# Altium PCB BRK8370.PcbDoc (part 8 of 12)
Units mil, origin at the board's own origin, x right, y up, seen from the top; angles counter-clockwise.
Board outline 8267.72 x 5708.66 mil, 6 copper layers (L1-TOP, L2-GND, L3-PWR, L4-PWR, L5-GND, L6-BOT), stack 68.606 mil thick; 319 components, 516 nets, 2008 pads, 1743 vias.
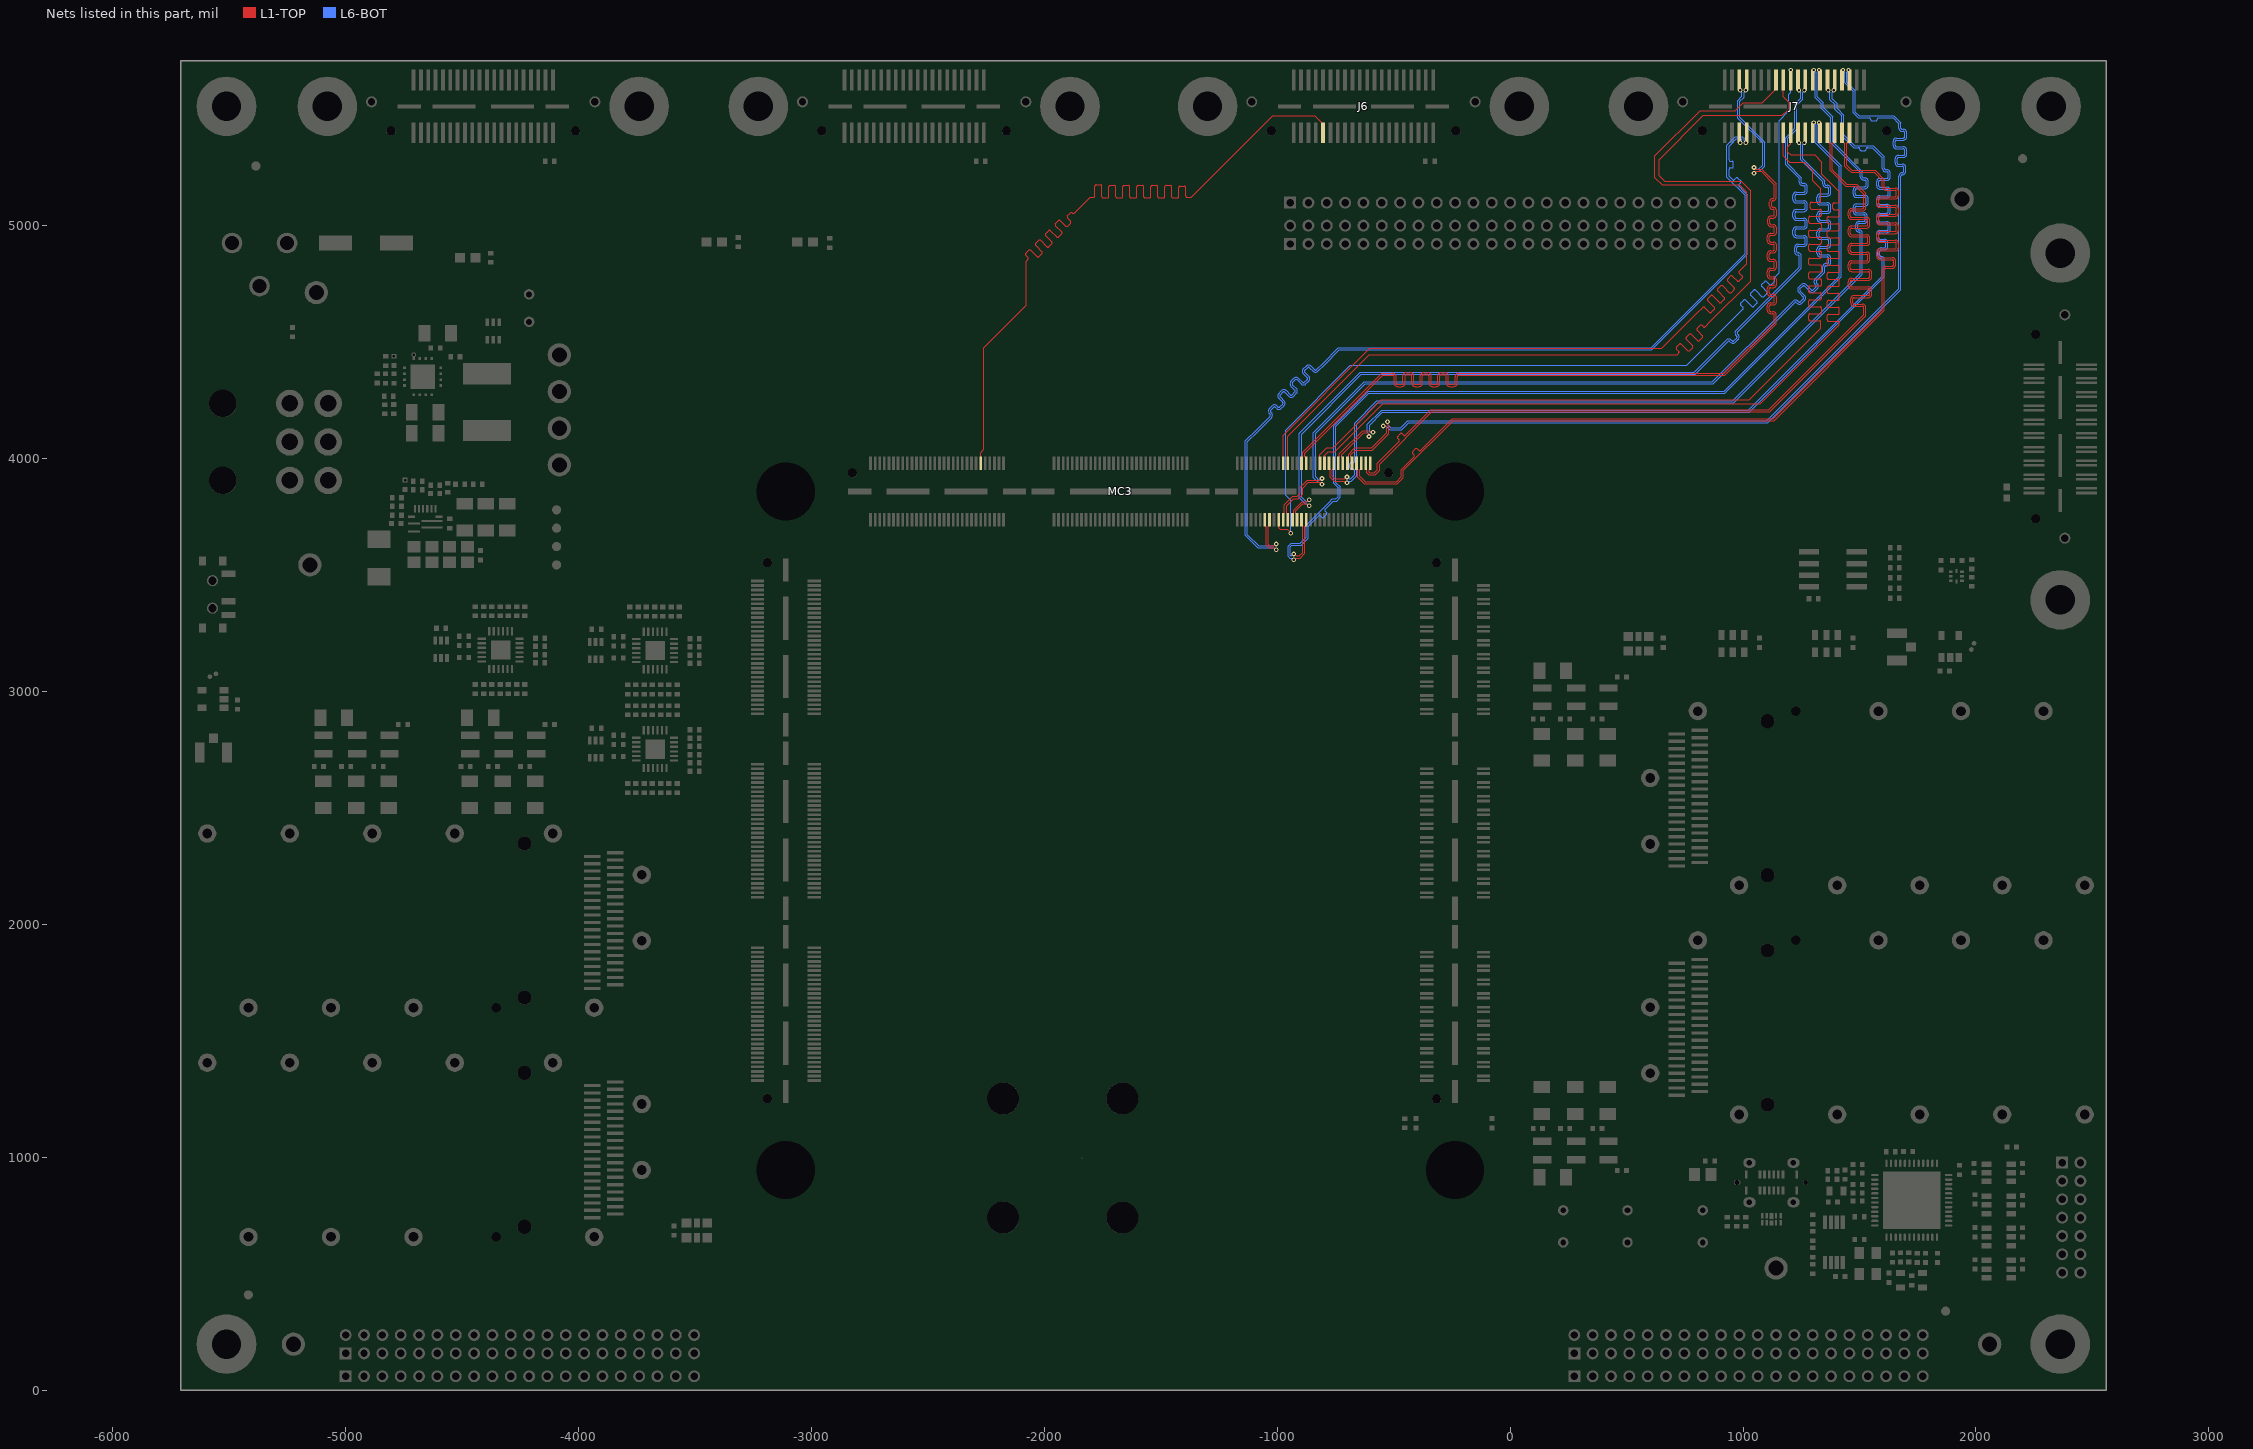
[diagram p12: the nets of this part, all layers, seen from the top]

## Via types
v1: diameter 20, hole 10, L1-TOP to L6-BOT, tented both sides, 957 vias
v2: diameter 18, hole 10, L1-TOP to L6-BOT, tented both sides, 786 vias

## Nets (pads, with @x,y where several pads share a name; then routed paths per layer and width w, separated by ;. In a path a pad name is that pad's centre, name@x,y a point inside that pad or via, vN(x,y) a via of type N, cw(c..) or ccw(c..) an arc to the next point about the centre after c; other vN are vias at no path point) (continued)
PORTC_S27: J6.32 MC3.49 | length 3564.2
  L1-TOP w4.96: MC3.49@-2273.62,3979.92 -2273.62,4025.59 -2259.84,4039.37 -2259.84,4476.38 -2078.74,4657.48 -2078.74,4846.46 -2072.15,4853.04 -2070.4,4854.8 ccw(c-2074.64,4859.03) -2070.4,4863.27 -2079.6,4872.48 cw(c-2075.36,4876.71) -2079.6,4880.95 -2066.89,4893.66 cw(c-2062.65,4889.42) -2058.42,4893.66 -2031.53,4866.78 ccw(c-2027.3,4871.02) -2023.06,4866.78 -2010.35,4879.49 ccw(c-2014.59,4883.73) -2010.35,4887.97 -2037.23,4914.85 cw(c-2032.99,4919.09) -2037.23,4923.32 -2024.52,4936.04 cw(c-2020.28,4931.8) -2016.04,4936.04 -1989.16,4909.16 ccw(c-1984.92,4913.39) -1980.69,4909.16 -1967.97,4921.87 ccw(c-1972.21,4926.1) -1967.97,4930.34 -1994.85,4957.22 cw(c-1990.62,4961.46) -1994.85,4965.7 -1982.14,4978.41 cw(c-1977.9,4974.17) -1973.67,4978.41 -1946.79,4951.53 ccw(c-1942.55,4955.77) -1938.31,4951.53 -1925.6,4964.24 ccw(c-1929.84,4968.48) -1925.6,4972.72 -1952.48,4999.6 cw(c-1948.24,5003.83) -1952.48,5008.07 -1939.77,5020.78 cw(c-1935.53,5016.55) -1931.29,5020.78 -1908.72,4998.21 ccw(c-1904.49,5002.45) -1900.25,4998.21 -1887.54,5010.93 ccw(c-1891.77,5015.16) -1887.54,5019.4 -1900.9,5032.77 cw(c-1896.67,5037.01) -1900.9,5041.24 -1888.19,5053.96 cw(c-1883.95,5049.72) -1879.72,5053.96 ccw(c-1875.48,5058.19) -1871.24,5053.96 -1842.52,5082.68 -1803.15,5122.05 -1791.34,5122.05 -1788.86,5122.05 ccw(c-1788.86,5128.04) -1782.86,5128.04 -1782.86,5169.34 cw(c-1776.87,5169.34) -1776.87,5175.33 -1758.89,5175.33 cw(c-1758.89,5169.34) -1752.9,5169.34 -1752.9,5124.78 ccw(c-1746.91,5124.78) -1746.91,5118.79 -1728.93,5118.79 ccw(c-1728.93,5124.78) -1722.94,5124.78 -1722.94,5166.24 cw(c-1716.95,5166.24) -1716.95,5172.23 -1698.97,5172.23 cw(c-1698.97,5166.24) -1692.98,5166.24 -1692.98,5124.78 ccw(c-1686.98,5124.78) -1686.98,5118.79 -1669,5118.79 ccw(c-1669,5124.78) -1663.01,5124.78 -1663.01,5166.24 cw(c-1657.02,5166.24) -1657.02,5172.23 -1639.04,5172.23 cw(c-1639.04,5166.24) -1633.05,5166.24 -1633.05,5124.78 ccw(c-1627.06,5124.78) -1627.06,5118.79 -1609.08,5118.79 ccw(c-1609.08,5124.78) -1603.09,5124.78 -1603.09,5166.24 cw(c-1597.09,5166.24) -1597.09,5172.23 -1579.12,5172.23 cw(c-1579.12,5166.24) -1573.12,5166.24 -1573.12,5124.78 ccw(c-1567.13,5124.78) -1567.13,5118.79 -1549.15,5118.79 ccw(c-1549.15,5124.78) -1543.16,5124.78 -1543.16,5166.24 cw(c-1537.17,5166.24) -1537.17,5172.23 -1519.19,5172.23 cw(c-1519.19,5166.24) -1513.2,5166.24 -1513.2,5124.78 ccw(c-1507.2,5124.78) -1507.2,5118.79 -1489.23,5118.79 ccw(c-1489.23,5124.78) -1483.23,5124.78 -1483.23,5166.24 cw(c-1477.24,5166.24) -1477.24,5172.23 -1459.26,5172.23 cw(c-1459.26,5166.24) -1453.27,5166.24 -1453.27,5124.78 ccw(c-1447.28,5124.78) -1447.28,5118.79 -1429.3,5118.79 ccw(c-1429.3,5124.78) -1423.31,5124.78 -1423.31,5163.15 cw(c-1417.32,5163.15) -1417.32,5169.14 -1399.34,5169.14 cw(c-1399.34,5163.15) -1393.35,5163.15 -1393.34,5128.04 ccw(c-1387.35,5128.04) -1387.35,5122.05 -1375.98,5122.05 -1369.15,5122.05 -1018.76,5472.44 -839.8,5472.44 -803.12,5435.76 J6.32@-803.12,5399.01
PORTD_C2P_CLK_N: J7.36 MC3.136 | length 4066.2
  L1-TOP w3.3: MC3.136@-1033.46,3736.61 -1033.46,3713.98 -1038.81,3708.63 -1038.81,3631.7 -1031.96,3624.86 -1014.22,3624.86 -1006.22,3632.86 v1(-1003.94,3632.86)
  L6-BOT w3.3: v1(-1003.94,3632.86) -1006.22,3632.86 -1014.22,3624.86 -1079.21,3624.86 -1127.75,3673.4 -1127.75,4072.12 -1080.25,4119.62 -1024.53,4175.34 ccw(c-1034.9,4185.7) -1023.22,4194.56 -1023.22,4194.75 -1024.52,4196.05 -1025.6,4197.13 -1028.03,4199.56 cw(c-1024.03,4203.57) -1028.03,4207.57 -1016.02,4219.57 cw(c-1012.02,4215.57) -1008.02,4219.57 -1003.18,4214.74 ccw(c-992.79,4225.08) -982.42,4214.71 -970.38,4226.75 ccw(c-980.78,4237.08) -969.1,4245.94 -969.1,4246.13 -987.48,4264.52 cw(c-983.48,4268.51) -987.48,4272.52 -975.47,4284.52 cw(c-971.47,4280.52) -967.46,4284.51 ; -967.44,4284.49 -950.43,4267.49 ccw(c-940.04,4277.83) -929.67,4267.46 -917.63,4279.5 ccw(c-928.03,4289.83) -916.35,4298.69 -916.35,4298.88 -934.73,4317.27 cw(c-930.73,4321.26) -934.73,4325.27 -922.72,4337.27 cw(c-918.72,4333.27) -914.71,4337.26 ; -914.69,4337.24 -897.68,4320.24 ccw(c-887.29,4330.58) -876.92,4320.21 -864.88,4332.25 ccw(c-875.28,4342.58) -863.6,4351.44 -863.6,4351.63 -881.98,4370.02 cw(c-877.98,4374.01) -881.98,4378.02 -869.97,4390.02 cw(c-865.97,4386.02) -861.96,4390.01 ; -861.94,4389.99 -846.27,4374.33 ccw(c-835.91,4384.7) -825.54,4374.33 -794.82,4405.05 -733.62,4466.25 608.9,4466.25 1018.66,4876.01 1018.66,5133.29 1004.01,5147.94 982.83,5169.12 cw(c986.84,5173.12) 982.83,5177.12 989.47,5183.76 ccw(c985.47,5187.76) 989.47,5191.76 977.46,5203.77 ccw(c973.46,5199.77) 969.46,5203.77 962.82,5197.13 cw(c958.82,5201.14) 954.82,5197.13 946.45,5205.5 939.82,5212.13 939.82,5242.08 cw(c945.48,5242.08) 945.48,5247.74 953,5247.74 ccw(c953,5253.4) 958.66,5253.4 958.66,5270.38 ccw(c953,5270.38) 953,5276.04 945.48,5276.04 cw(c945.48,5281.7) 939.82,5281.7 939.82,5303.15 939.82,5341.23 971.27,5372.68 993.59,5372.68 995.52,5370.75 995.52,5364.94 988.49,5357.9 v2(988.49,5355.65)
PORTD_C2P_CLK_P: J7.34 MC3.134 | length 4066.2
  L1-TOP w3.3: MC3.134@-1053.15,3736.61 -1053.15,3713.98 -1047.81,3708.63 -1047.81,3627.98 -1035.69,3615.86 -1014.22,3615.86 -1006.22,3607.86 v1(-1003.94,3607.86)
  L6-BOT w3.3: v1(-1003.94,3607.86) -1006.22,3607.86 -1014.22,3615.86 -1082.93,3615.86 -1136.75,3669.68 -1136.75,4075.85 -1086.61,4125.98 -1030.9,4181.7 ccw(c-1034.9,4185.7) -1030.92,4189.72 -1034.39,4193.2 cw(c-1024.03,4203.57) -1034.39,4213.93 -1022.35,4225.98 cw(c-1012.02,4215.57) -1001.66,4225.94 -998.28,4222.56 -996.79,4221.07 ccw(c-992.79,4225.08) -988.79,4221.08 -976.78,4233.08 ccw(c-980.78,4237.08) -976.79,4241.1 ; -976.81,4241.12 -993.81,4258.12 cw(c-983.48,4268.51) -993.84,4278.88 -981.8,4290.92 cw(c-971.47,4280.52) -962.62,4292.21 -962.42,4292.21 -944.04,4273.82 ccw(c-940.04,4277.83) -936.04,4273.83 -924.03,4285.83 ccw(c-928.03,4289.83) -924.04,4293.85 ; -924.06,4293.87 -941.06,4310.87 cw(c-930.73,4321.26) -941.09,4331.63 -929.05,4343.67 cw(c-918.72,4333.27) -909.87,4344.96 -909.67,4344.96 -891.29,4326.57 ccw(c-887.29,4330.58) -883.29,4326.58 -871.28,4338.58 ccw(c-875.28,4342.58) -871.29,4346.6 ; -871.31,4346.62 -888.31,4363.62 cw(c-877.98,4374.01) -888.34,4384.38 -876.3,4396.42 cw(c-865.97,4386.02) -857.12,4397.71 -856.92,4397.71 -839.91,4380.69 ccw(c-835.91,4384.7) -831.91,4380.69 -801.18,4411.42 -737.35,4475.25 605.17,4475.25 1009.66,4879.74 1009.66,5129.56 930.82,5208.4 930.82,5344.96 967.55,5381.68 997.32,5381.68 1004.52,5374.48 1004.52,5364.94 1011.56,5357.9 v2(1011.56,5355.65)
PORTD_P2C_CLK_N: J7.35 MC3.151 | length 4066.2
  L1-TOP w3.3: MC3.151@-875.98,3979.92 -875.98,4002.56 -881.33,4007.9 -881.33,4022.72 -546.81,4357.23 -531.5,4357.23 -503.23,4357.23 cw(c-503.23,4351.57) -497.57,4351.57 -497.57,4323.62 ccw(c-482.91,4323.62) -482.91,4308.96 -465.93,4308.96 ccw(c-465.93,4323.62) -451.27,4323.62 -451.27,4354.28 cw(c-445.61,4354.28) -445.61,4359.94 -428.63,4359.94 cw(c-428.63,4354.28) -422.97,4354.28 -422.97,4323.62 ccw(c-408.31,4323.62) -408.31,4308.96 -391.33,4308.96 ccw(c-391.33,4323.62) -376.67,4323.62 -376.67,4354.28 cw(c-371.01,4354.28) -371.01,4359.94 -354.03,4359.94 cw(c-354.03,4354.28) -348.37,4354.28 -348.37,4323.62 ccw(c-333.71,4323.62) -333.71,4308.96 -316.73,4308.96 ccw(c-316.73,4323.62) -302.07,4323.62 -302.07,4354.28 cw(c-296.41,4354.28) -296.41,4359.94 -279.43,4359.94 cw(c-279.43,4354.28) -273.77,4354.28 -273.77,4323.62 ccw(c-259.11,4323.62) -259.11,4308.96 -242.13,4308.96 ccw(c-242.13,4323.62) -227.47,4323.62 -227.47,4351.57 cw(c-221.81,4351.57) -221.81,4357.23 -215.66,4357.23 921.14,4357.23 1142.86,4578.95 1142.86,4610.24 1142.86,4616.39 ccw(c1128.2,4616.39) 1128.2,4631.05 1118.81,4631.05 cw(c1118.81,4636.71) 1113.15,4636.71 1113.15,4653.69 cw(c1118.81,4653.69) 1118.81,4659.35 1129.4,4659.35 ccw(c1129.4,4674.01) 1144.06,4674.01 1144.06,4690.99 ccw(c1129.4,4690.99) 1129.4,4705.65 1118.81,4705.65 cw(c1118.81,4711.31) 1113.15,4711.31 1113.15,4728.29 cw(c1118.81,4728.29) 1118.81,4733.95 1129.4,4733.95 ccw(c1129.4,4748.61) 1144.06,4748.61 1144.06,4765.59 ccw(c1129.4,4765.59) 1129.4,4780.25 1118.81,4780.25 cw(c1118.81,4785.91) 1113.15,4785.91 1113.15,4802.89 cw(c1118.81,4802.89) 1118.81,4808.55 1129.4,4808.55 ccw(c1129.4,4823.21) 1144.06,4823.21 1144.06,4840.19 ccw(c1129.4,4840.19) 1129.4,4854.85 1118.81,4854.85 cw(c1118.81,4860.51) 1113.15,4860.51 1113.15,4877.49 cw(c1118.81,4877.49) 1118.81,4883.15 1129.4,4883.15 ccw(c1129.4,4897.81) 1144.06,4897.81 1144.06,4914.79 ccw(c1129.4,4914.79) 1129.4,4929.45 1118.81,4929.45 cw(c1118.81,4935.11) 1113.15,4935.11 1113.15,4952.09 cw(c1118.81,4952.09) 1118.81,4957.75 1129.4,4957.75 ccw(c1129.4,4972.41) 1144.06,4972.41 1144.06,4989.39 ccw(c1129.4,4989.39) 1129.4,5004.05 1121.1,5004.05 cw(c1121.1,5009.71) 1115.44,5009.71 1115.44,5026.69 cw(c1121.1,5026.69) 1121.1,5032.35 1129.4,5032.35 ccw(c1129.4,5047.01) 1144.06,5047.01 1144.06,5063.99 ccw(c1129.4,5063.99) 1129.4,5078.65 1128.2,5078.65 cw(c1128.2,5084.31) 1122.54,5084.31 1122.54,5101.29 cw(c1128.2,5101.29) 1128.2,5106.95 ccw(c1128.2,5121.61) 1142.86,5121.61 1142.86,5165.91 1142.86,5179.87 1081.32,5241.41 1057.53,5241.41 1049.53,5249.41 v1(1047.24,5249.41)
  L6-BOT w3.3: v2(988.49,5581.25) 988.49,5579.01 995.52,5571.97 995.52,5554.8 977.5,5536.78 977.5,5461.1 1083.8,5354.8 1083.8,5259.38 1065.84,5241.41 1057.53,5241.41 1049.53,5249.41 v1(1047.24,5249.41)
PORTD_P2C_CLK_P: J7.33 MC3.149 | length 4066.2
  L1-TOP w3.3: MC3.149@-895.67,3979.92 -895.67,4002.56 -890.33,4007.9 -890.33,4026.44 -550.54,4366.23 -531.5,4366.23 -503.23,4366.23 cw(c-503.23,4351.57) -488.57,4351.57 -488.57,4323.62 ccw(c-482.91,4323.62) -482.91,4317.96 -465.93,4317.96 ccw(c-465.93,4323.62) -460.27,4323.62 -460.27,4354.28 cw(c-445.61,4354.28) -445.61,4368.94 -428.63,4368.94 cw(c-428.63,4354.28) -413.97,4354.28 -413.97,4323.62 ccw(c-408.31,4323.62) -408.31,4317.96 -391.33,4317.96 ccw(c-391.33,4323.62) -385.67,4323.62 -385.67,4354.28 cw(c-371.01,4354.28) -371.01,4368.94 -354.03,4368.94 cw(c-354.03,4354.28) -339.37,4354.28 -339.37,4323.62 ccw(c-333.71,4323.62) -333.71,4317.96 -316.73,4317.96 ccw(c-316.73,4323.62) -311.07,4323.62 -311.07,4354.28 cw(c-296.41,4354.28) -296.41,4368.94 -279.43,4368.94 cw(c-279.43,4354.28) -264.77,4354.28 -264.77,4323.62 ccw(c-259.11,4323.62) -259.11,4317.96 -242.13,4317.96 ccw(c-242.13,4323.62) -236.47,4323.62 -236.47,4351.57 cw(c-221.81,4351.57) -221.81,4366.23 -215.66,4366.23 917.41,4366.23 1133.86,4582.68 1133.86,4610.24 1133.86,4616.39 ccw(c1128.2,4616.39) 1128.2,4622.05 1118.81,4622.05 cw(c1118.81,4636.71) 1104.15,4636.71 1104.15,4653.69 cw(c1118.81,4653.69) 1118.81,4668.35 1129.4,4668.35 ccw(c1129.4,4674.01) 1135.06,4674.01 1135.06,4690.99 ccw(c1129.4,4690.99) 1129.4,4696.65 1118.81,4696.65 cw(c1118.81,4711.31) 1104.15,4711.31 1104.15,4728.29 cw(c1118.81,4728.29) 1118.81,4742.95 1129.4,4742.95 ccw(c1129.4,4748.61) 1135.06,4748.61 1135.06,4765.59 ccw(c1129.4,4765.59) 1129.4,4771.25 1118.81,4771.25 cw(c1118.81,4785.91) 1104.15,4785.91 1104.15,4802.89 cw(c1118.81,4802.89) 1118.81,4817.55 1129.4,4817.55 ccw(c1129.4,4823.21) 1135.06,4823.21 1135.06,4840.19 ccw(c1129.4,4840.19) 1129.4,4845.85 1118.81,4845.85 cw(c1118.81,4860.51) 1104.15,4860.51 1104.15,4877.49 cw(c1118.81,4877.49) 1118.81,4892.15 1129.4,4892.15 ccw(c1129.4,4897.81) 1135.06,4897.81 1135.06,4914.79 ccw(c1129.4,4914.79) 1129.4,4920.45 1118.81,4920.45 cw(c1118.81,4935.11) 1104.15,4935.11 1104.15,4952.09 cw(c1118.81,4952.09) 1118.81,4966.75 1129.4,4966.75 ccw(c1129.4,4972.41) 1135.06,4972.41 1135.06,4989.39 ccw(c1129.4,4989.39) 1129.4,4995.05 1121.1,4995.05 cw(c1121.1,5009.71) 1106.44,5009.71 1106.44,5026.69 cw(c1121.1,5026.69) 1121.1,5041.35 1129.4,5041.35 ccw(c1129.4,5047.01) 1135.06,5047.01 1135.06,5063.99 ccw(c1129.4,5063.99) 1129.4,5069.65 1128.2,5069.65 cw(c1128.2,5084.31) 1113.54,5084.31 1113.54,5101.29 cw(c1128.2,5101.29) 1128.2,5115.95 ccw(c1128.2,5121.61) 1133.86,5121.61 1133.86,5165.91 1133.86,5176.14 1077.59,5232.41 1057.53,5232.41 1049.53,5224.41 v1(1047.24,5224.41)
  L6-BOT w3.3: v2(1011.56,5581.25) 1011.56,5579.01 1004.52,5571.97 1004.52,5551.07 986.5,5533.05 986.5,5464.82 1092.8,5358.52 1092.8,5255.65 1069.56,5232.41 1057.53,5232.41 1049.53,5224.41 v1(1047.24,5224.41)
PORTD_S0_D0_P: J7.5 MC3.169 | length 4066
  L1-TOP w3.3: MC3.169@-698.82,3979.92 -698.82,4002.56 -693.48,4007.9 -693.48,4019.26 -667.42,4045.32 -594.82,4045.32 -529.5,4110.64 -529.5,4136.18 -531.52,4138.2 -542.84,4138.2 v1(-544.45,4139.82)
  L6-BOT w3.3: v1(-544.45,4139.82) -542.84,4138.2 -531.52,4138.2 -516.53,4123.21 -465.69,4123.21 -436.2,4152.7 1106.37,4152.7 1678.29,4724.62 1678.29,5161.42 1678.29,5212.23 cw(c1683.95,5212.23) 1683.95,5217.89 ccw(c1683.95,5232.55) 1698.61,5232.55 1698.61,5249.53 ccw(c1683.95,5249.53) 1683.95,5264.19 1667.32,5264.19 cw(c1667.32,5269.85) 1661.66,5269.85 1661.66,5286.83 cw(c1667.32,5286.83) 1667.32,5292.49 1688.63,5292.49 ccw(c1688.63,5307.15) 1703.29,5307.15 1703.29,5324.13 ccw(c1688.63,5324.13) 1688.63,5338.79 1658.95,5338.79 cw(c1658.95,5344.45) 1653.29,5344.45 1653.29,5361.43 cw(c1658.95,5361.43) 1658.95,5367.09 1688.63,5367.09 ccw(c1688.63,5381.75) 1703.29,5381.75 1703.29,5398.73 ccw(c1688.63,5398.73) 1688.63,5413.39 1683.95,5413.39 cw(c1683.95,5419.05) 1678.29,5419.05 1678.29,5425.2 1678.29,5440.74 1647.89,5471.14 1498.28,5471.14 1481.94,5487.48 1481.94,5579.62 1445.52,5616.04 1445.52,5658.69 1452.56,5665.72 v2(1452.56,5667.97)
PORTD_S1_D1_P: J7.6 MC3.173 | length 4247.7
  L1-TOP w3.3: MC3.173@-659.45,3979.92 -659.45,3957.28 -654.11,3951.94 -654.11,3919.32 -626.24,3891.45 -484,3891.45 -458.38,3917.07 -458.38,3948.56 -244.58,4162.36 1134.15,4162.36 1607.43,4635.63 1607.43,4643.06 1607.43,4811.06 cw(c1613.09,4811.06) 1613.09,4816.72 1640.58,4816.72 ccw(c1640.58,4831.38) 1655.24,4831.38 1655.24,4848.36 ccw(c1640.58,4848.36) 1640.58,4863.02 1588.09,4863.02 cw(c1588.09,4868.68) 1582.43,4868.68 1582.43,4885.66 cw(c1588.09,4885.66) 1588.09,4891.32 1652.97,4891.32 ccw(c1652.97,4905.98) 1667.63,4905.98 1667.63,4922.96 ccw(c1652.97,4922.96) 1652.97,4937.62 1588.09,4937.62 cw(c1588.09,4943.28) 1582.43,4943.28 1582.43,4960.26 cw(c1588.09,4960.26) 1588.09,4965.92 1652.97,4965.92 ccw(c1652.97,4980.58) 1667.63,4980.58 1667.63,4997.56 ccw(c1652.97,4997.56) 1652.97,5012.22 1588.09,5012.22 cw(c1588.09,5017.88) 1582.43,5017.88 1582.43,5034.86 cw(c1588.09,5034.86) 1588.09,5040.52 1652.97,5040.52 ccw(c1652.97,5055.18) 1667.63,5055.18 1667.63,5072.16 ccw(c1652.97,5072.16) 1652.97,5086.82 1588.09,5086.82 cw(c1588.09,5092.48) 1582.43,5092.48 1582.43,5109.46 cw(c1588.09,5109.46) 1588.09,5115.12 1652.97,5115.12 ccw(c1652.97,5129.78) 1667.63,5129.78 1667.63,5146.76 ccw(c1652.97,5146.76) 1652.97,5161.42 1613.09,5161.42 cw(c1613.09,5167.08) 1607.43,5167.08 1607.43,5173.23 1607.43,5196.64 1566.72,5237.35 1467.38,5237.35 1445.52,5259.2 1445.52,5353.98 1447.46,5355.91 1450.42,5355.91 1456.77,5362.26 J7.6@1456.77,5399.01
PORTD_S2_D0_N: J7.7 MC3.171 | length 4066
  L1-TOP w3.3: MC3.171@-679.13,3979.92 -679.13,4002.56 -684.48,4007.9 -684.48,4015.53 -663.69,4036.32 -591.09,4036.32 -520.5,4106.91 -520.5,4139.91 -525.16,4144.57 -525.16,4155.88 v1(-526.78,4157.49)
  L6-BOT w3.3: v1(-526.78,4157.49) -525.16,4155.88 -525.16,4144.57 -512.8,4132.21 -469.42,4132.21 -439.93,4161.7 1102.65,4161.7 1669.29,4728.35 1669.29,5161.42 1669.29,5212.23 cw(c1683.95,5212.23) 1683.95,5226.89 ccw(c1683.95,5232.55) 1689.61,5232.55 1689.61,5249.53 ccw(c1683.95,5249.53) 1683.95,5255.19 1667.32,5255.19 cw(c1667.32,5269.85) 1652.66,5269.85 1652.66,5286.83 cw(c1667.32,5286.83) 1667.32,5301.49 1688.63,5301.49 ccw(c1688.63,5307.15) 1694.29,5307.15 1694.29,5324.13 ccw(c1688.63,5324.13) 1688.63,5329.79 1658.95,5329.79 cw(c1658.95,5344.45) 1644.29,5344.45 1644.29,5361.43 cw(c1658.95,5361.43) 1658.95,5376.09 1688.63,5376.09 ccw(c1688.63,5381.75) 1694.29,5381.75 1694.29,5398.73 ccw(c1688.63,5398.73) 1688.63,5404.39 1683.95,5404.39 cw(c1683.95,5419.05) 1669.29,5419.05 1669.29,5425.2 1669.29,5437.01 1665.35,5440.94 1644.16,5462.14 1583.12,5462.14 1581.47,5462.14 ccw(c1581.47,5456.48) 1575.81,5456.48 1575.81,5455.49 cw(c1570.15,5455.49) 1570.15,5449.83 1553.17,5449.83 cw(c1553.17,5455.49) 1547.51,5455.49 1547.51,5456.48 ccw(c1541.85,5456.48) 1541.85,5462.14 1511.57,5462.14 1494.55,5462.14 1488.19,5468.5 1472.94,5483.75 1472.94,5575.89 1436.52,5612.31 1436.52,5658.69 1429.49,5665.72 v2(1429.49,5667.97)
PORTD_S3_D1_N: J7.8 MC3.175 | length 4247.7
  L1-TOP w3.3: MC3.175@-639.76,3979.92 -639.76,3957.28 -645.11,3951.94 -645.11,3923.04 -622.51,3900.45 -487.72,3900.45 -467.38,3920.79 -467.38,3952.29 -424.13,3995.53 -412.57,4007.1 ccw(c-416.57,4011.1) -412.57,4015.1 -418.55,4021.08 cw(c-414.54,4025.08) -418.55,4029.08 -406.54,4041.09 cw(c-402.54,4037.09) -398.54,4041.09 -392.56,4035.11 ccw(c-388.56,4039.12) -384.56,4035.11 -363.38,4056.29 -248.31,4171.36 1130.42,4171.36 1598.43,4639.36 1598.43,4643.06 1598.43,4811.06 cw(c1613.09,4811.06) 1613.09,4825.72 1640.58,4825.72 ccw(c1640.58,4831.38) 1646.24,4831.38 1646.24,4848.36 ccw(c1640.58,4848.36) 1640.58,4854.02 1588.09,4854.02 cw(c1588.09,4868.68) 1573.43,4868.68 1573.43,4885.66 cw(c1588.09,4885.66) 1588.09,4900.32 1652.97,4900.32 ccw(c1652.97,4905.98) 1658.63,4905.98 1658.63,4922.96 ccw(c1652.97,4922.96) 1652.97,4928.62 1588.09,4928.62 cw(c1588.09,4943.28) 1573.43,4943.28 1573.43,4960.26 cw(c1588.09,4960.26) 1588.09,4974.92 1652.97,4974.92 ccw(c1652.97,4980.58) 1658.63,4980.58 1658.63,4997.56 ccw(c1652.97,4997.56) 1652.97,5003.22 1588.09,5003.22 cw(c1588.09,5017.88) 1573.43,5017.88 1573.43,5034.86 cw(c1588.09,5034.86) 1588.09,5049.52 1652.97,5049.52 ccw(c1652.97,5055.18) 1658.63,5055.18 1658.63,5072.16 ccw(c1652.97,5072.16) 1652.97,5077.82 1588.09,5077.82 cw(c1588.09,5092.48) 1573.43,5092.48 1573.43,5109.46 cw(c1588.09,5109.46) 1588.09,5124.12 1652.97,5124.12 ccw(c1652.97,5129.78) 1658.63,5129.78 1658.63,5146.76 ccw(c1652.97,5146.76) 1652.97,5152.42 1613.09,5152.42 cw(c1613.09,5167.08) 1598.43,5167.08 1598.43,5173.23 1598.43,5192.91 1562.99,5228.35 1463.65,5228.35 1454.27,5237.73 1436.52,5255.47 1436.52,5353.98 1434.59,5355.91 1431.62,5355.91 1425.27,5362.26 J7.8@1425.27,5399.01
PORTD_S4_D2_P: J7.9 MC3.165 | length 4066
  L1-TOP w3.3: MC3.165@-738.19,3979.92 -738.19,4002.56 -732.85,4007.9 -732.85,4019.94 -632.83,4119.96 -619.37,4119.96 -619.19,4120.14 -607.91,4120.14 -601.55,4113.78 -590.24,4113.78 v1(-588.62,4112.17)
  L6-BOT w3.3: v1(-588.62,4112.17) -590.24,4113.78 -601.55,4113.78 -603.57,4115.8 -603.57,4142.98 -548.21,4198.33 1026.02,4198.33 1607.43,4779.74 1607.43,4814.96 1607.43,4852.5 ccw(c1592.77,4852.5) 1592.77,4867.16 cw(c1592.76,4872.82) 1587.1,4872.82 1587.1,4889.8 cw(c1592.76,4889.8) 1592.76,4895.46 1606.71,4895.46 ccw(c1606.71,4910.12) 1621.37,4910.12 1621.37,4927.1 ccw(c1606.71,4927.1) 1606.71,4941.76 1588.09,4941.76 cw(c1588.09,4947.42) 1582.43,4947.42 1582.43,4964.4 cw(c1588.09,4964.4) 1588.09,4970.06 1617.77,4970.06 ccw(c1617.77,4984.72) 1632.43,4984.72 1632.43,5001.7 ccw(c1617.77,5001.7) 1617.77,5016.36 1588.09,5016.36 cw(c1588.09,5022.02) 1582.43,5022.02 1582.43,5039 cw(c1588.09,5039) 1588.09,5044.66 1617.77,5044.66 ccw(c1617.77,5059.32) 1632.43,5059.32 1632.43,5076.3 ccw(c1617.77,5076.3) 1617.77,5090.96 1588.09,5090.96 cw(c1588.09,5096.62) 1582.43,5096.62 1582.43,5113.6 cw(c1588.09,5113.6) 1588.09,5119.26 1617.77,5119.26 ccw(c1617.77,5133.92) 1632.43,5133.92 1632.43,5150.9 ccw(c1617.77,5150.9) 1617.77,5165.56 1588.09,5165.56 cw(c1588.09,5171.22) 1582.43,5171.22 1582.43,5188.2 cw(c1588.09,5188.2) 1588.09,5193.86 1617.77,5193.86 ccw(c1617.77,5208.52) 1632.43,5208.52 1632.43,5225.5 ccw(c1617.77,5225.5) 1617.77,5240.16 1613.09,5240.16 cw(c1613.09,5245.82) 1607.43,5245.82 1607.43,5251.97 1607.43,5295.07 1594.42,5308.07 1558.8,5343.69 1480.06,5343.69 1433.4,5390.35 1433.4,5474.62 1403.74,5504.27 1403.74,5523.8 1382.42,5545.12 1382.42,5571.97 1389.46,5579.01 v2(1389.46,5581.25)
PORTD_S5_D3_P: J7.10 MC3.177 | length 4247.7
  L1-TOP w3.3: MC3.177@-620.08,3979.92 -620.08,3957.28 -614.74,3951.94 -614.74,3937.68 -607.53,3930.48 -578.83,3930.48 -560.74,3948.56 -560.74,3976.12 -337.2,4199.66 1113.96,4199.66 1527.56,4613.26 1527.56,4625.98 1527.56,4647.98 ccw(c1512.9,4647.98) 1512.9,4662.64 1477.15,4662.64 cw(c1477.15,4668.3) 1471.49,4668.3 1471.49,4685.28 cw(c1477.15,4685.28) 1477.15,4690.94 1537.9,4690.94 ccw(c1537.9,4705.6) 1552.56,4705.6 1552.56,4722.58 ccw(c1537.9,4722.58) 1537.9,4737.24 1466.37,4737.24 cw(c1466.37,4742.9) 1460.71,4742.9 1460.71,4759.88 cw(c1466.37,4759.88) 1466.37,4765.54 1537.9,4765.54 ccw(c1537.9,4780.2) 1552.56,4780.2 1552.56,4797.18 ccw(c1537.9,4797.18) 1537.9,4811.84 1466.37,4811.84 cw(c1466.37,4817.5) 1460.71,4817.5 1460.71,4834.48 cw(c1466.37,4834.48) 1466.37,4840.14 1530.47,4840.14 ccw(c1530.47,4854.8) 1545.13,4854.8 1545.13,4871.78 ccw(c1530.47,4871.78) 1530.47,4886.44 1466.37,4886.44 cw(c1466.37,4892.1) 1460.71,4892.1 1460.71,4909.08 cw(c1466.37,4909.08) 1466.37,4914.74 1530.47,4914.74 ccw(c1530.47,4929.4) 1545.13,4929.4 1545.13,4946.38 ccw(c1530.47,4946.38) 1530.47,4961.04 1466.37,4961.04 cw(c1466.37,4966.7) 1460.71,4966.7 1460.71,4983.68 cw(c1466.37,4983.68) 1466.37,4989.34 1530.47,4989.34 ccw(c1530.47,5004) 1545.13,5004 1545.13,5020.98 ccw(c1530.47,5020.98) 1530.47,5035.64 1466.37,5035.64 cw(c1466.37,5041.3) 1460.71,5041.3 1460.71,5058.28 cw(c1466.37,5058.28) 1466.37,5063.94 1512.9,5063.94 ccw(c1512.9,5078.6) 1527.56,5078.6 1527.56,5122.05 1527.56,5138.71 1487.98,5178.29 1444.67,5178.29 1443.38,5179.59 1382.52,5240.44 1382.52,5353.98 1384.46,5355.91 1387.42,5355.91 1393.77,5362.26 J7.10@1393.77,5399.01
PORTD_S6_D2_N: J7.11 MC3.167 | length 4066
  L1-TOP w3.3: MC3.167@-718.5,3979.92 -718.5,4002.56 -723.85,4007.9 -723.85,4016.21 -629.1,4110.96 -615.64,4110.96 -615.46,4111.14 -611.64,4111.14 -607.91,4107.42 -607.91,4096.1 v1(-606.3,4094.49)
  L6-BOT w3.3: v1(-606.3,4094.49) -607.91,4096.1 -607.91,4107.42 -612.57,4112.07 -612.57,4146.71 -551.94,4207.33 1022.3,4207.33 1598.43,4783.46 1598.43,4814.96 1598.43,4852.5 ccw(c1592.77,4852.5) 1592.77,4858.16 cw(c1592.76,4872.82) 1578.1,4872.82 1578.1,4889.8 cw(c1592.76,4889.8) 1592.76,4904.46 1606.71,4904.46 ccw(c1606.71,4910.12) 1612.37,4910.12 1612.37,4927.1 ccw(c1606.71,4927.1) 1606.71,4932.76 1588.09,4932.76 cw(c1588.09,4947.42) 1573.43,4947.42 1573.43,4964.4 cw(c1588.09,4964.4) 1588.09,4979.06 1617.77,4979.06 ccw(c1617.77,4984.72) 1623.43,4984.72 1623.43,5001.7 ccw(c1617.77,5001.7) 1617.77,5007.36 1588.09,5007.36 cw(c1588.09,5022.02) 1573.43,5022.02 1573.43,5039 cw(c1588.09,5039) 1588.09,5053.66 1617.77,5053.66 ccw(c1617.77,5059.32) 1623.43,5059.32 1623.43,5076.3 ccw(c1617.77,5076.3) 1617.77,5081.96 1588.09,5081.96 cw(c1588.09,5096.62) 1573.43,5096.62 1573.43,5113.6 cw(c1588.09,5113.6) 1588.09,5128.26 1617.77,5128.26 ccw(c1617.77,5133.92) 1623.43,5133.92 1623.43,5150.9 ccw(c1617.77,5150.9) 1617.77,5156.56 1588.09,5156.56 cw(c1588.09,5171.22) 1573.43,5171.22 1573.43,5188.2 cw(c1588.09,5188.2) 1588.09,5202.86 1617.77,5202.86 ccw(c1617.77,5208.52) 1623.43,5208.52 1623.43,5225.5 ccw(c1617.77,5225.5) 1617.77,5231.16 1613.09,5231.16 cw(c1613.09,5245.82) 1598.43,5245.82 1598.43,5251.97 1598.43,5291.34 1581.69,5308.07 1555.07,5334.69 1536.48,5334.69 1534.83,5334.69 ccw(c1534.83,5329.03) 1529.17,5329.03 1529.17,5328.03 cw(c1523.51,5328.03) 1523.51,5322.37 1506.53,5322.37 cw(c1506.53,5328.03) 1500.87,5328.03 1500.87,5329.03 ccw(c1495.21,5329.03) 1495.21,5334.69 1482.83,5334.69 1476.33,5334.69 1473.7,5337.33 1424.4,5386.63 1424.4,5470.9 1394.74,5500.55 1394.74,5520.07 1373.42,5541.39 1373.42,5571.97 1366.39,5579.01 v2(1366.39,5581.25)
PORTD_S7_D3_N: J7.12 MC3.179 | length 4247.7
  L1-TOP w3.3: MC3.179@-600.39,3979.92 -600.39,3957.28 -605.74,3951.94 -605.74,3941.41 -603.8,3939.48 -582.55,3939.48 -569.74,3952.29 -569.74,3979.85 -501.17,4048.42 -477.53,4072.06 ccw(c-481.53,4076.06) -477.53,4080.06 -483.51,4086.04 cw(c-479.51,4090.04) -483.51,4094.04 -471.5,4106.05 cw(c-467.5,4102.05) -463.5,4106.05 -457.52,4100.07 ccw(c-453.52,4104.08) -449.52,4100.07 -428.34,4121.25 -340.93,4208.66 1110.24,4208.66 1518.56,4616.98 1518.56,4625.98 1518.56,4647.98 ccw(c1512.9,4647.98) 1512.9,4653.64 1477.15,4653.64 cw(c1477.15,4668.3) 1462.49,4668.3 1462.49,4685.28 cw(c1477.15,4685.28) 1477.15,4699.94 1537.9,4699.94 ccw(c1537.9,4705.6) 1543.56,4705.6 1543.56,4722.58 ccw(c1537.9,4722.58) 1537.9,4728.24 1466.37,4728.24 cw(c1466.37,4742.9) 1451.71,4742.9 1451.71,4759.88 cw(c1466.37,4759.88) 1466.37,4774.54 1537.9,4774.54 ccw(c1537.9,4780.2) 1543.56,4780.2 1543.56,4797.18 ccw(c1537.9,4797.18) 1537.9,4802.84 1466.37,4802.84 cw(c1466.37,4817.5) 1451.71,4817.5 1451.71,4834.48 cw(c1466.37,4834.48) 1466.37,4849.14 1530.47,4849.14 ccw(c1530.47,4854.8) 1536.13,4854.8 1536.13,4871.78 ccw(c1530.47,4871.78) 1530.47,4877.44 1466.37,4877.44 cw(c1466.37,4892.1) 1451.71,4892.1 1451.71,4909.08 cw(c1466.37,4909.08) 1466.37,4923.74 1530.47,4923.74 ccw(c1530.47,4929.4) 1536.13,4929.4 1536.13,4946.38 ccw(c1530.47,4946.38) 1530.47,4952.04 1466.37,4952.04 cw(c1466.37,4966.7) 1451.71,4966.7 1451.71,4983.68 cw(c1466.37,4983.68) 1466.37,4998.34 1530.47,4998.34 ccw(c1530.47,5004) 1536.13,5004 1536.13,5020.98 ccw(c1530.47,5020.98) 1530.47,5026.64 1466.37,5026.64 cw(c1466.37,5041.3) 1451.71,5041.3 1451.71,5058.28 cw(c1466.37,5058.28) 1466.37,5072.94 1512.9,5072.94 ccw(c1512.9,5078.6) 1518.56,5078.6 1518.56,5122.05 1518.56,5134.98 1484.25,5169.29 1440.94,5169.29 1373.52,5236.71 1373.52,5353.98 1371.59,5355.91 1368.62,5355.91 1362.27,5362.26 J7.12@1362.27,5399.01
PORTD_S8_D4_P: J7.13 MC3.161 | length 4066.2
  L1-TOP w3.3: MC3.161@-777.56,3979.92 -777.56,3957.28 -772.22,3951.94 -772.22,3919.32 -756.16,3903.26 -711.07,3903.26 -703.07,3895.26 v1(-700.79,3895.26)
  L6-BOT w3.3: v1(-700.79,3895.26) -698.5,3895.26 -690.5,3903.26 -681.51,3903.26 -659.17,3925.61 -659.17,4148.06 -568.24,4238.98 960.37,4238.98 1512.94,4791.55 1512.94,4887.14 1512.94,4966.26 ccw(c1498.28,4966.26) 1498.28,4980.92 cw(c1498.28,4986.58) 1492.62,4986.58 1492.62,5003.56 cw(c1498.28,5003.56) 1498.28,5009.22 1519.08,5009.22 ccw(c1519.08,5023.88) 1533.74,5023.88 1533.74,5040.86 ccw(c1519.08,5040.86) 1519.08,5055.52 1487.1,5055.52 cw(c1487.1,5061.18) 1481.44,5061.18 1481.44,5078.16 cw(c1487.1,5078.16) 1487.1,5083.82 1523.28,5083.82 ccw(c1523.28,5098.48) 1537.94,5098.48 1537.94,5115.46 ccw(c1523.28,5115.46) 1523.28,5130.12 1487.1,5130.12 cw(c1487.1,5135.78) 1481.44,5135.78 1481.44,5152.76 cw(c1487.1,5152.76) 1487.1,5158.42 1523.28,5158.42 ccw(c1523.28,5173.08) 1537.94,5173.08 1537.94,5190.06 ccw(c1523.28,5190.06) 1523.28,5204.72 1518.6,5204.72 cw(c1518.6,5210.38) 1512.94,5210.38 1512.94,5216.54 1512.94,5232.07 1384.7,5360.31 1384.7,5467.48 1344.77,5507.41 1344.77,5527.65 1319.52,5552.9 1319.52,5658.69 1326.56,5665.72 v2(1326.56,5667.97)
PORTD_S9_D5_P: J7.14 MC3.150 | length 4066
  L1-TOP w3.3: v1(-929.13,3589.55) -926.85,3589.55 -918.85,3581.55 -905.05,3581.55 -890.33,3596.27 -890.33,3708.63 -895.67,3713.98 MC3.150@-895.67,3736.61
  L6-BOT w3.3: v1(-929.13,3589.55) -931.42,3589.55 -939.42,3581.55 -942.28,3581.55 -944.21,3583.49 -944.21,3620.37 -936.7,3627.89 -897.16,3627.89 -866.82,3658.23 -866.82,3709.57 -843.66,3732.73 -822.49,3753.91 cw(c-818.48,3749.91) -814.48,3753.91 -808.51,3747.93 ccw(c-804.5,3751.94) -800.5,3747.93 -788.49,3759.94 ccw(c-792.5,3763.94) -788.49,3767.94 -794.47,3773.92 cw(c-790.47,3777.92) -794.47,3781.92 -769.69,3806.7 -759.06,3817.34 -745.43,3817.34 -730.03,3832.73 -730.03,3878.21 -748.16,3896.34 -748.16,4055.12 -748.16,4137.69 -606.22,4279.63 922.28,4279.63 1422.39,4779.74 1422.39,5256.51 1370.82,5308.07 1319.52,5359.37 1319.52,5433.09 1326.56,5440.12 v2(1326.56,5442.37)
PORTD_S10_D4_N: J7.15 MC3.163 | length 4066.2
  L1-TOP w3.3: MC3.163@-757.87,3979.92 -757.87,3957.28 -763.22,3951.94 -763.22,3923.04 -752.43,3912.26 -711.07,3912.26 -703.07,3920.26 v1(-700.79,3920.26)
  L6-BOT w3.3: v1(-700.79,3920.26) -698.5,3920.26 -690.5,3912.26 -685.24,3912.26 -668.17,3929.33 -668.17,3946.69 -668.17,3948.34 ccw(c-673.83,3948.34) -673.83,3954 -682.28,3954 cw(c-682.28,3959.66) -687.94,3959.66 -687.94,3976.64 cw(c-682.28,3976.64) -682.28,3982.3 -673.83,3982.3 ccw(c-673.83,3987.96) -668.17,3987.96 -668.17,4015.75 -668.17,4151.79 -571.97,4247.98 956.65,4247.98 1503.94,4795.28 1503.94,4887.14 1503.94,4966.26 ccw(c1498.28,4966.26) 1498.28,4971.92 cw(c1498.28,4986.58) 1483.62,4986.58 1483.62,5003.56 cw(c1498.28,5003.56) 1498.28,5018.22 1519.08,5018.22 ccw(c1519.08,5023.88) 1524.74,5023.88 1524.74,5040.86 ccw(c1519.08,5040.86) 1519.08,5046.52 1487.1,5046.52 cw(c1487.1,5061.18) 1472.44,5061.18 1472.44,5078.16 cw(c1487.1,5078.16) 1487.1,5092.82 1523.28,5092.82 ccw(c1523.28,5098.48) 1528.94,5098.48 1528.94,5115.46 ccw(c1523.28,5115.46) 1523.28,5121.12 1487.1,5121.12 cw(c1487.1,5135.78) 1472.44,5135.78 1472.44,5152.76 cw(c1487.1,5152.76) 1487.1,5167.42 1523.28,5167.42 ccw(c1523.28,5173.08) 1528.94,5173.08 1528.94,5190.06 ccw(c1523.28,5190.06) 1523.28,5195.72 1518.6,5195.72 cw(c1518.6,5210.38) 1503.94,5210.38 1503.94,5216.54 1503.94,5228.35 1375.7,5356.58 1375.7,5463.75 1335.77,5503.68 1335.77,5523.93 1310.52,5549.17 1310.52,5658.69 1303.49,5665.72 v2(1303.49,5667.97)
PORTD_S11_D5_N: J7.16 MC3.152 | length 4066
  L1-TOP w3.3: v1(-929.13,3564.55) -926.85,3564.55 -918.85,3572.55 -901.32,3572.55 -881.33,3592.54 -881.33,3708.63 -875.98,3713.98 MC3.152@-875.98,3736.61
  L6-BOT w3.3: v1(-929.13,3564.55) -931.42,3564.55 -939.42,3572.55 -946,3572.55 -953.21,3579.76 -953.21,3624.1 -940.42,3636.89 -900.89,3636.89 -875.82,3661.96 -875.82,3713.3 -776.05,3813.07 -762.78,3826.34 -749.15,3826.34 -739.03,3836.46 -739.03,3874.48 -757.16,3892.61 -757.16,4055.12 -757.16,4141.42 -609.94,4288.63 918.56,4288.63 1413.39,4783.46 1413.39,5252.78 1358.1,5308.07 1310.52,5355.65 1310.52,5433.09 1303.49,5440.12 v2(1303.49,5442.37)
PORTD_S12_D6_P: J7.17 MC3.146 | length 4066.1
  L1-TOP w3.3: MC3.146@-935.04,3736.61 -935.04,3759.25 -929.7,3764.59 -929.7,3778.51 -893.68,3814.53 -872.49,3814.53 -864.49,3822.53 v1(-862.2,3822.53)
  L6-BOT w3.3: v1(-862.2,3822.53) -864.49,3822.53 -872.49,3814.53 -876.09,3814.53 -895.72,3834.15 -895.72,4105.11 -639.89,4360.93 794.01,4360.93 872.84,4439.77 935.28,4502.21 cw(c939.28,4498.2) 943.3,4502.19 ; 943.31,4502.18 946.61,4498.88 ccw(c956.97,4509.24) 967.34,4498.88 979.38,4510.92 ccw(c968.98,4521.25) 979.35,4531.62 978.05,4532.91 976.01,4534.95 cw(c980.02,4538.95) 976.02,4542.95 980.37,4547.3 1250.85,4817.78 1250.85,4826.77 1250.85,4868.04 ccw(c1236.19,4868.04) 1236.19,4882.7 1236.06,4882.7 cw(c1236.06,4888.36) 1230.4,4888.36 1230.4,4905.34 cw(c1236.06,4905.34) 1236.06,4911 1261.19,4911 ccw(c1261.19,4925.66) 1275.85,4925.66 1275.85,4942.64 ccw(c1261.19,4942.64) 1261.19,4957.3 1228.84,4957.3 cw(c1228.84,4962.96) 1223.18,4962.96 1223.18,4979.94 cw(c1228.84,4979.94) 1228.84,4985.6 1261.19,4985.6 ccw(c1261.19,5000.26) 1275.85,5000.26 1275.85,5017.24 ccw(c1261.19,5017.24) 1261.19,5031.9 1228.84,5031.9 cw(c1228.84,5037.56) 1223.18,5037.56 1223.18,5054.54 cw(c1228.84,5054.54) 1228.84,5060.2 1261.19,5060.2 ccw(c1261.19,5074.86) 1275.85,5074.86 1275.85,5091.84 ccw(c1261.19,5091.84) 1261.19,5106.5 1228.84,5106.5 cw(c1228.84,5112.16) 1223.18,5112.16 1223.18,5129.14 cw(c1228.84,5129.14) 1228.84,5134.8 1261.19,5134.8 ccw(c1261.19,5149.46) 1275.85,5149.46 1275.85,5166.44 ccw(c1261.19,5166.44) 1261.19,5181.1 1256.51,5181.1 cw(c1256.51,5186.76) 1250.85,5186.76 1250.85,5192.91 1250.85,5206.23 1191.79,5265.29 1191.79,5374.32 1231.16,5413.69 1231.16,5516.77 1256.42,5542.04 1256.42,5571.97 1263.46,5579.01 v2(1263.46,5581.25)
PORTD_S13_D7_P: J7.18 MC3.142 | length 4066.2
  L1-TOP w3.3: MC3.142@-974.41,3736.61 -974.41,3759.25 -969.07,3764.59 -969.07,3801.33 -933.5,3836.9 -913.6,3836.9 -900.45,3850.05 -900.45,3876.68 -870.88,3906.24 -818.35,3906.24 -810.35,3914.24 v1(-808.07,3914.24)
  L6-BOT w3.3: v1(-808.07,3914.24) -810.35,3914.24 -818.35,3906.24 -821.21,3906.24 -835.73,3920.76 -835.73,4107.61 -623.05,4320.28 872.38,4320.28 1182.61,4630.52 1221.51,4669.42 cw(c1225.52,4665.41) 1229.54,4669.4 ; 1229.54,4669.39 1232.25,4666.69 ccw(c1242.61,4677.05) 1252.98,4666.69 1265.02,4678.73 ccw(c1254.62,4689.06) 1264.98,4699.43 1250.81,4713.61 1244.57,4719.84 cw(c1248.58,4723.83) 1244.58,4727.84 1256.59,4739.84 cw(c1260.59,4735.84) 1264.6,4739.83 1286.77,4717.66 ccw(c1297.17,4728) 1307.53,4717.63 1319.58,4729.68 ccw(c1309.17,4740.01) 1320.86,4748.86 1320.86,4749.05 1315.01,4754.9 cw(c1319.01,4758.91) 1315.01,4762.91 1319.36,4767.26 1351.52,4799.42 1351.52,4822.87 cw(c1357.18,4822.87) 1357.18,4828.53 1361.86,4828.53 ccw(c1361.86,4843.19) 1376.52,4843.19 1376.52,4860.17 ccw(c1361.86,4860.17) 1361.86,4874.83 1332.18,4874.83 cw(c1332.18,4880.49) 1326.52,4880.49 1326.52,4897.47 cw(c1332.18,4897.47) 1332.18,4903.13 1361.86,4903.13 ccw(c1361.86,4917.79) 1376.52,4917.79 1376.52,4934.77 ccw(c1361.86,4934.77) 1361.86,4949.43 1332.18,4949.43 cw(c1332.18,4955.09) 1326.52,4955.09 1326.52,4972.07 cw(c1332.18,4972.07) 1332.18,4977.73 1361.86,4977.73 ccw(c1361.86,4992.39) 1376.52,4992.39 1376.52,5009.37 ccw(c1361.86,5009.37) 1361.86,5024.03 1332.18,5024.03 cw(c1332.18,5029.69) 1326.52,5029.69 1326.52,5046.67 cw(c1332.18,5046.67) 1332.18,5052.33 1361.86,5052.33 ccw(c1361.86,5066.99) 1376.52,5066.99 1376.52,5083.97 ccw(c1361.86,5083.97) 1361.86,5098.63 1332.18,5098.63 cw(c1332.18,5104.29) 1326.52,5104.29 1326.52,5121.27 cw(c1332.18,5121.27) 1332.18,5126.93 1361.86,5126.93 ccw(c1361.86,5141.59) 1376.52,5141.59 1376.52,5158.57 ccw(c1361.86,5158.57) 1361.86,5173.23 1357.18,5173.23 cw(c1357.18,5178.89) 1351.52,5178.89 1351.52,5185.04 1351.52,5191.79 1313.45,5229.86 1256.52,5286.78 1256.52,5346.37 1263.56,5353.41 v2(1263.56,5355.65)
PORTD_S14_D6_N: J7.19 MC3.148 | length 4066.2
  L1-TOP w3.3: MC3.148@-915.35,3736.61 -915.35,3759.25 -920.7,3764.59 -920.7,3774.78 -889.95,3805.53 -872.49,3805.53 -864.49,3797.53 v1(-862.2,3797.53)
  L6-BOT w3.3: v1(-862.2,3797.53) -864.49,3797.53 -872.49,3805.53 -879.82,3805.53 -904.72,3830.42 -904.72,4108.84 -643.62,4369.93 790.28,4369.93 866.48,4446.13 928.91,4508.57 cw(c939.28,4498.2) 948.13,4509.89 948.33,4509.89 949.63,4508.59 950.66,4507.55 952.97,4505.24 ccw(c956.97,4509.24) 960.98,4505.24 972.98,4517.25 ccw(c968.98,4521.25) 972.98,4525.25 969.68,4528.56 cw(c980.02,4538.95) 969.66,4549.31 974,4553.66 1241.85,4821.51 1241.85,4826.77 1241.85,4868.04 ccw(c1236.19,4868.04) 1236.19,4873.7 1236.06,4873.7 cw(c1236.06,4888.36) 1221.4,4888.36 1221.4,4905.34 cw(c1236.06,4905.34) 1236.06,4920 1261.19,4920 ccw(c1261.19,4925.66) 1266.85,4925.66 1266.85,4942.64 ccw(c1261.19,4942.64) 1261.19,4948.3 1228.84,4948.3 cw(c1228.84,4962.96) 1214.18,4962.96 1214.18,4979.94 cw(c1228.84,4979.94) 1228.84,4994.6 1261.19,4994.6 ccw(c1261.19,5000.26) 1266.85,5000.26 1266.85,5017.24 ccw(c1261.19,5017.24) 1261.19,5022.9 1228.84,5022.9 cw(c1228.84,5037.56) 1214.18,5037.56 1214.18,5054.54 cw(c1228.84,5054.54) 1228.84,5069.2 1261.19,5069.2 ccw(c1261.19,5074.86) 1266.85,5074.86 1266.85,5091.84 ccw(c1261.19,5091.84) 1261.19,5097.5 1228.84,5097.5 cw(c1228.84,5112.16) 1214.18,5112.16 1214.18,5129.14 cw(c1228.84,5129.14) 1228.84,5143.8 1261.19,5143.8 ccw(c1261.19,5149.46) 1266.85,5149.46 1266.85,5166.44 ccw(c1261.19,5166.44) 1261.19,5172.1 1256.51,5172.1 cw(c1256.51,5186.76) 1241.85,5186.76 1241.85,5192.91 1241.85,5202.5 1182.79,5261.56 1182.79,5378.05 1222.16,5417.42 1222.16,5520.5 1247.42,5545.77 1247.42,5571.97 1240.39,5579.01 v2(1240.39,5581.25)
PORTD_S15_D7_N: J7.20 MC3.144 | length 4066.3
  L1-TOP w3.3: MC3.144@-954.72,3736.61 -954.72,3759.25 -960.07,3764.59 -960.07,3797.61 -929.78,3827.9 -909.87,3827.9 -891.45,3846.32 -891.45,3872.95 -867.16,3897.24 -818.35,3897.24 -810.35,3889.24 v1(-808.07,3889.24)
  L6-BOT w3.3: v1(-808.07,3889.24) -810.35,3889.24 -818.35,3897.24 -824.94,3897.24 -844.73,3917.03 -844.73,4111.34 -626.78,4329.28 868.65,4329.28 1176.25,4636.88 1215.15,4675.78 cw(c1225.52,4665.41) 1234.37,4677.1 1234.56,4677.1 1235.86,4675.8 ; 1235.88,4675.78 1236.71,4674.95 1238.61,4673.05 ccw(c1242.61,4677.05) 1246.61,4673.05 1258.62,4685.06 ccw(c1254.62,4689.06) 1258.62,4693.06 1238.24,4713.44 ; 1238.24,4713.44 cw(c1248.58,4723.83) 1238.22,4734.2 1250.26,4746.24 cw(c1260.59,4735.84) 1269.44,4747.53 1269.64,4747.53 1293.17,4723.99 ccw(c1297.17,4728) 1301.17,4724 1313.18,4736 ccw(c1309.17,4740.01) 1313.16,4744.02 ; v2(1240.49,5355.65) 1240.49,5353.41 1247.52,5346.37 1247.52,5283.06 1300.72,5229.86 1342.52,5188.06 1342.52,5185.04 1342.52,5178.89 ccw(c1357.18,5178.89) 1357.18,5164.23 1361.86,5164.23 cw(c1361.86,5158.57) 1367.52,5158.57 1367.52,5141.59 cw(c1361.86,5141.59) 1361.86,5135.93 1332.18,5135.93 ccw(c1332.18,5121.27) 1317.52,5121.27 1317.52,5104.29 ccw(c1332.18,5104.29) 1332.18,5089.63 1361.86,5089.63 cw(c1361.86,5083.97) 1367.52,5083.97 1367.52,5066.99 cw(c1361.86,5066.99) 1361.86,5061.33 1332.18,5061.33 ccw(c1332.18,5046.67) 1317.52,5046.67 1317.52,5029.69 ccw(c1332.18,5029.69) 1332.18,5015.03 1361.86,5015.03 cw(c1361.86,5009.37) 1367.52,5009.37 1367.52,4992.39 cw(c1361.86,4992.39) 1361.86,4986.73 1332.18,4986.73 ccw(c1332.18,4972.07) 1317.52,4972.07 1317.52,4955.09 ccw(c1332.18,4955.09) 1332.18,4940.43 1361.86,4940.43 cw(c1361.86,4934.77) 1367.52,4934.77 1367.52,4917.79 cw(c1361.86,4917.79) 1361.86,4912.13 1332.18,4912.13 ccw(c1332.18,4897.47) 1317.52,4897.47 1317.52,4880.49 ccw(c1332.18,4880.49) 1332.18,4865.83 1361.86,4865.83 cw(c1361.86,4860.17) 1367.52,4860.17 1367.52,4843.19 cw(c1361.86,4843.19) 1361.86,4837.53 1357.18,4837.53 ccw(c1357.18,4822.87) 1342.52,4822.87 1342.52,4803.15 1338.79,4799.42 1312.99,4773.62 1308.64,4769.27 ccw(c1319.01,4758.91) 1308.64,4748.54 1313.15,4744.04
PORTD_S16: J7.21 MC3.140 | length 4064.5
  L1-TOP w4.96: MC3.140@-994.09,3736.61 -994.09,3702.76 -987.41,3696.07 -956.03,3696.07 -942.28,3682.32 v1(-942.28,3678.96)
  L6-BOT w4.96: v1(-942.28,3678.96) -942.28,3819.66 -964.57,3841.94 -964.57,4121.13 -686.24,4399.46 757.72,4399.46 997.61,4639.35 999.37,4641.1 ccw(c995.13,4645.34) 999.37,4649.58 990.17,4658.78 cw(c994.4,4663.02) 990.17,4667.25 1002.88,4679.97 cw(c1007.12,4675.73) 1011.35,4679.97 1038.23,4653.09 ccw(c1042.47,4657.32) 1046.71,4653.09 1059.42,4665.8 ccw(c1055.18,4670.03) 1059.42,4674.27 1032.54,4701.15 cw(c1036.78,4705.39) 1032.54,4709.63 1045.25,4722.34 cw(c1049.49,4718.1) 1053.73,4722.34 1080.61,4695.46 ccw(c1084.85,4699.7) 1089.08,4695.46 1101.79,4708.17 ccw(c1097.56,4712.41) 1101.79,4716.65 1079.72,4738.72 cw(c1083.96,4742.96) 1079.72,4747.2 1092.43,4759.91 cw(c1096.67,4755.67) 1100.9,4759.91 1113.78,4747.04 ccw(c1118.02,4751.27) 1122.25,4747.04 1134.97,4759.75 ccw(c1130.73,4763.99) 1134.97,4768.22 cw(c1139.2,4772.46) 1134.97,4776.7 1145.67,4787.4 1155.61,4797.34 1155.61,5450.89 1196.85,5492.13 1196.85,5564.04 1204.67,5571.86 v2(1204.67,5667.97)
PORTD_S17: J7.22 MC3.159 | length 4242.4
  L1-TOP w4.96: MC3.159@-797.24,3979.92 -797.24,4012.26 -781.12,4028.38 -753.98,4028.38 -547.36,4235.01 1073.59,4235.01 1413.39,4574.8 1413.39,4580.71 1413.39,4583.19 ccw(c1407.39,4583.19) 1407.39,4589.18 1367.91,4589.18 cw(c1367.91,4595.18) 1361.92,4595.18 1361.92,4613.15 cw(c1367.91,4613.15) 1367.91,4619.15 1407.44,4619.15 ccw(c1407.44,4625.14) 1413.43,4625.14 1413.43,4643.12 ccw(c1407.44,4643.12) 1407.44,4649.11 1367.91,4649.11 cw(c1367.91,4655.1) 1361.92,4655.1 1361.92,4673.08 cw(c1367.91,4673.08) 1367.91,4679.07 1407.44,4679.07 ccw(c1407.44,4685.06) 1413.43,4685.06 1413.43,4703.04 ccw(c1407.44,4703.04) 1407.44,4709.04 1367.91,4709.04 cw(c1367.91,4715.03) 1361.92,4715.03 1361.92,4733.01 cw(c1367.91,4733.01) 1367.91,4739 1407.44,4739 ccw(c1407.44,4744.99) 1413.43,4744.99 1413.43,4762.97 ccw(c1407.44,4762.97) 1407.44,4768.96 1367.91,4768.96 cw(c1367.91,4774.95) 1361.92,4774.95 1361.92,4792.93 cw(c1367.91,4792.93) 1367.91,4798.92 1407.44,4798.92 ccw(c1407.44,4804.92) 1413.43,4804.92 1413.43,4822.89 ccw(c1407.44,4822.89) 1407.44,4828.89 1367.91,4828.89 cw(c1367.91,4834.88) 1361.92,4834.88 1361.92,4852.86 cw(c1367.91,4852.86) 1367.91,4858.85 1407.44,4858.85 ccw(c1407.44,4864.84) 1413.43,4864.84 1413.43,4882.82 ccw(c1407.44,4882.82) 1407.44,4888.81 1367.91,4888.81 cw(c1367.91,4894.81) 1361.92,4894.81 1361.92,4912.78 cw(c1367.91,4912.78) 1367.91,4918.78 1407.44,4918.78 ccw(c1407.44,4924.77) 1413.43,4924.77 1413.43,4942.75 ccw(c1407.44,4942.75) 1407.44,4948.74 1367.91,4948.74 cw(c1367.91,4954.73) 1361.92,4954.73 1361.92,4972.71 cw(c1367.91,4972.71) 1367.91,4978.7 1407.44,4978.7 ccw(c1407.44,4984.69) 1413.43,4984.69 1413.43,5002.67 ccw(c1407.44,5002.67) 1407.44,5008.67 1367.91,5008.67 cw(c1367.91,5014.66) 1361.92,5014.66 1361.92,5032.64 cw(c1367.91,5032.64) 1367.91,5038.63 1407.44,5038.63 ccw(c1407.44,5044.62) 1413.43,5044.62 1413.43,5062.6 ccw(c1407.44,5062.6) 1407.44,5068.59 1392.22,5068.59 cw(c1392.22,5074.58) 1386.23,5074.58 1386.23,5092.56 cw(c1392.22,5092.56) 1392.22,5098.55 1407.39,5098.55 ccw(c1407.39,5104.55) 1413.39,5104.55 1413.39,5137.8 1413.39,5145.67 1338.58,5220.47 1338.58,5271.65 1307.09,5303.15 1204.72,5303.15 1192.91,5314.96 1192.91,5338.58 1204.77,5350.44 J7.22@1204.77,5399.01
PORTD_S18: J7.23 MC3.143 | length 4242.4
  L1-TOP w4.96: MC3.143@-954.72,3979.92 -954.72,4095.72 -605.56,4444.88 716.54,4444.88 721.58,4449.93 723.34,4451.68 ccw(c719.1,4455.92) 723.34,4460.16 714.13,4469.36 cw(c718.37,4473.6) 714.13,4477.83 726.85,4490.55 cw(c731.08,4486.31) 735.32,4490.55 762.2,4463.67 ccw(c766.44,4467.9) 770.68,4463.67 783.39,4476.38 ccw(c779.15,4480.62) 783.39,4484.85 756.51,4511.73 cw(c760.74,4515.97) 756.51,4520.21 769.22,4532.92 cw(c773.46,4528.68) 777.69,4532.92 804.57,4506.04 ccw(c808.81,4510.28) 813.05,4506.04 825.76,4518.75 ccw(c821.52,4522.99) 825.76,4527.23 803.02,4549.97 cw(c807.26,4554.21) 803.02,4558.44 815.73,4571.16 cw(c819.97,4566.92) 824.21,4571.16 829.27,4566.09 ccw(c833.51,4570.33) 837.75,4566.09 862.2,4590.55 1032.48,4760.83 1032.48,5150.68 991.76,5191.41 662.92,5191.41 640.09,5214.24 640.09,5283.36 829.76,5473.04 1168.28,5473.04 1195.45,5500.21 1195.45,5530.19 1173.27,5552.37 J7.23@1173.27,5624.61
PORTD_S19: J7.24 MC3.157 | length 4242.4
  L1-TOP w4.96: MC3.157@-816.93,3979.92 -816.93,4016.56 -788.15,4045.35 -761.01,4045.35 -751.23,4055.12 -554.38,4251.97 1027.56,4251.97 1334.65,4559.06 1334.65,4582.68 1334.65,4585.16 ccw(c1328.65,4585.16) 1328.65,4591.15 1287.58,4591.15 cw(c1287.58,4597.14) 1281.58,4597.14 1281.58,4615.12 cw(c1287.58,4615.12) 1287.58,4621.11 1331.02,4621.11 ccw(c1331.02,4627.11) 1337.01,4627.11 1337.01,4645.09 ccw(c1331.02,4645.09) 1331.02,4651.08 1287.58,4651.08 cw(c1287.58,4657.07) 1281.58,4657.07 1281.58,4675.05 cw(c1287.58,4675.05) 1287.58,4681.04 1331.02,4681.04 ccw(c1331.02,4687.03) 1337.01,4687.03 1337.01,4705.01 ccw(c1331.02,4705.01) 1331.02,4711 1287.58,4711 cw(c1287.58,4717) 1281.58,4717 1281.58,4734.97 cw(c1287.58,4734.97) 1287.58,4740.97 1331.02,4740.97 ccw(c1331.02,4746.96) 1337.01,4746.96 1337.01,4764.94 ccw(c1331.02,4764.94) 1331.02,4770.93 1287.58,4770.93 cw(c1287.58,4776.92) 1281.58,4776.92 1281.58,4794.9 cw(c1287.58,4794.9) 1287.58,4800.89 1331.02,4800.89 ccw(c1331.02,4806.89) 1337.01,4806.89 1337.01,4824.86 ccw(c1331.02,4824.86) 1331.02,4830.86 1287.58,4830.86 cw(c1287.58,4836.85) 1281.58,4836.85 1281.58,4854.83 cw(c1287.58,4854.83) 1287.58,4860.82 1331.02,4860.82 ccw(c1331.02,4866.81) 1337.01,4866.81 1337.01,4884.79 ccw(c1331.02,4884.79) 1331.02,4890.78 1287.58,4890.78 cw(c1287.58,4896.77) 1281.58,4896.77 1281.58,4914.75 cw(c1287.58,4914.75) 1287.58,4920.74 1331.02,4920.74 ccw(c1331.02,4926.74) 1337.01,4926.74 1337.01,4944.72 ccw(c1331.02,4944.72) 1331.02,4950.71 1287.58,4950.71 cw(c1287.58,4956.7) 1281.58,4956.7 1281.58,4974.68 cw(c1287.58,4974.68) 1287.58,4980.67 1331.02,4980.67 ccw(c1331.02,4986.66) 1337.01,4986.66 1337.01,5004.64 ccw(c1331.02,5004.64) 1331.02,5010.63 1287.58,5010.63 cw(c1287.58,5016.63) 1281.58,5016.63 1281.58,5034.6 cw(c1287.58,5034.6) 1287.58,5040.6 1331.02,5040.6 ccw(c1331.02,5046.59) 1337.01,5046.59 1337.01,5064.57 ccw(c1331.02,5064.57) 1331.02,5070.56 1294.86,5070.56 cw(c1294.86,5076.55) 1288.87,5076.55 1288.87,5094.53 cw(c1294.86,5094.53) 1294.86,5100.52 1328.65,5100.52 ccw(c1328.65,5106.52) 1334.65,5106.52 1334.65,5152.14 1334.65,5157.48 1299.21,5192.91 1299.21,5236.22 1263.78,5271.65 1200.79,5271.65 1173.27,5299.17 J7.24@1173.27,5399.01
PORTD_S20: J7.25 MC3.141 | length 4245
  L1-TOP w4.96: MC3.141@-974.41,3979.92 -974.41,4100.03 -602,4472.44 651.82,4472.44 804.26,4624.88 827.2,4647.82 cw(c831.44,4643.58) 835.67,4647.82 855.87,4627.62 ccw(c860.11,4631.86) 864.35,4627.62 877.06,4640.33 ccw(c872.82,4644.57) 877.06,4648.8 848.6,4677.26 cw(c852.84,4681.5) 848.6,4685.74 861.31,4698.45 cw(c865.55,4694.21) 869.79,4698.45 898.25,4669.99 ccw(c902.49,4674.23) 906.72,4669.99 919.44,4682.7 ccw(c915.2,4686.94) 919.44,4691.18 890.98,4719.64 cw(c895.21,4723.88) 890.98,4728.11 903.69,4740.83 cw(c907.93,4736.59) 912.16,4740.83 940.62,4712.37 ccw(c944.86,4716.6) 949.1,4712.37 961.81,4725.08 ccw(c957.57,4729.32) 961.81,4733.55 933.35,4762.01 cw(c937.59,4766.25) 933.35,4770.49 946.06,4783.2 cw(c950.3,4778.96) 954.54,4783.2 975.45,4762.29 ccw(c979.68,4766.53) 983.92,4762.29 996.63,4775 ccw(c992.4,4779.24) 996.63,4783.48 983.98,4796.13 cw(c988.22,4800.36) 983.98,4804.6 1011.61,4832.23 1015.52,4836.14 1015.52,5143.66 984.73,5174.44 652.7,5174.44 621.01,5206.13 621.01,5299.22 815.66,5493.87 965.95,5493.87 1000.32,5528.24 1082.15,5528.24 1141.77,5587.86 J7.25@1141.77,5624.61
